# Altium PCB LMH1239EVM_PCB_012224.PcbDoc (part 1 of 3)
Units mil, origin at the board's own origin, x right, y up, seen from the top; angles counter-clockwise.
Board outline 4000 x 4500 mil, 4 copper layers (Top Layer, L02_GND, L03_PWR, Bottom Layer), stack 61.395 mil thick; 161 components, 103 nets, 483 pads, 593 vias.
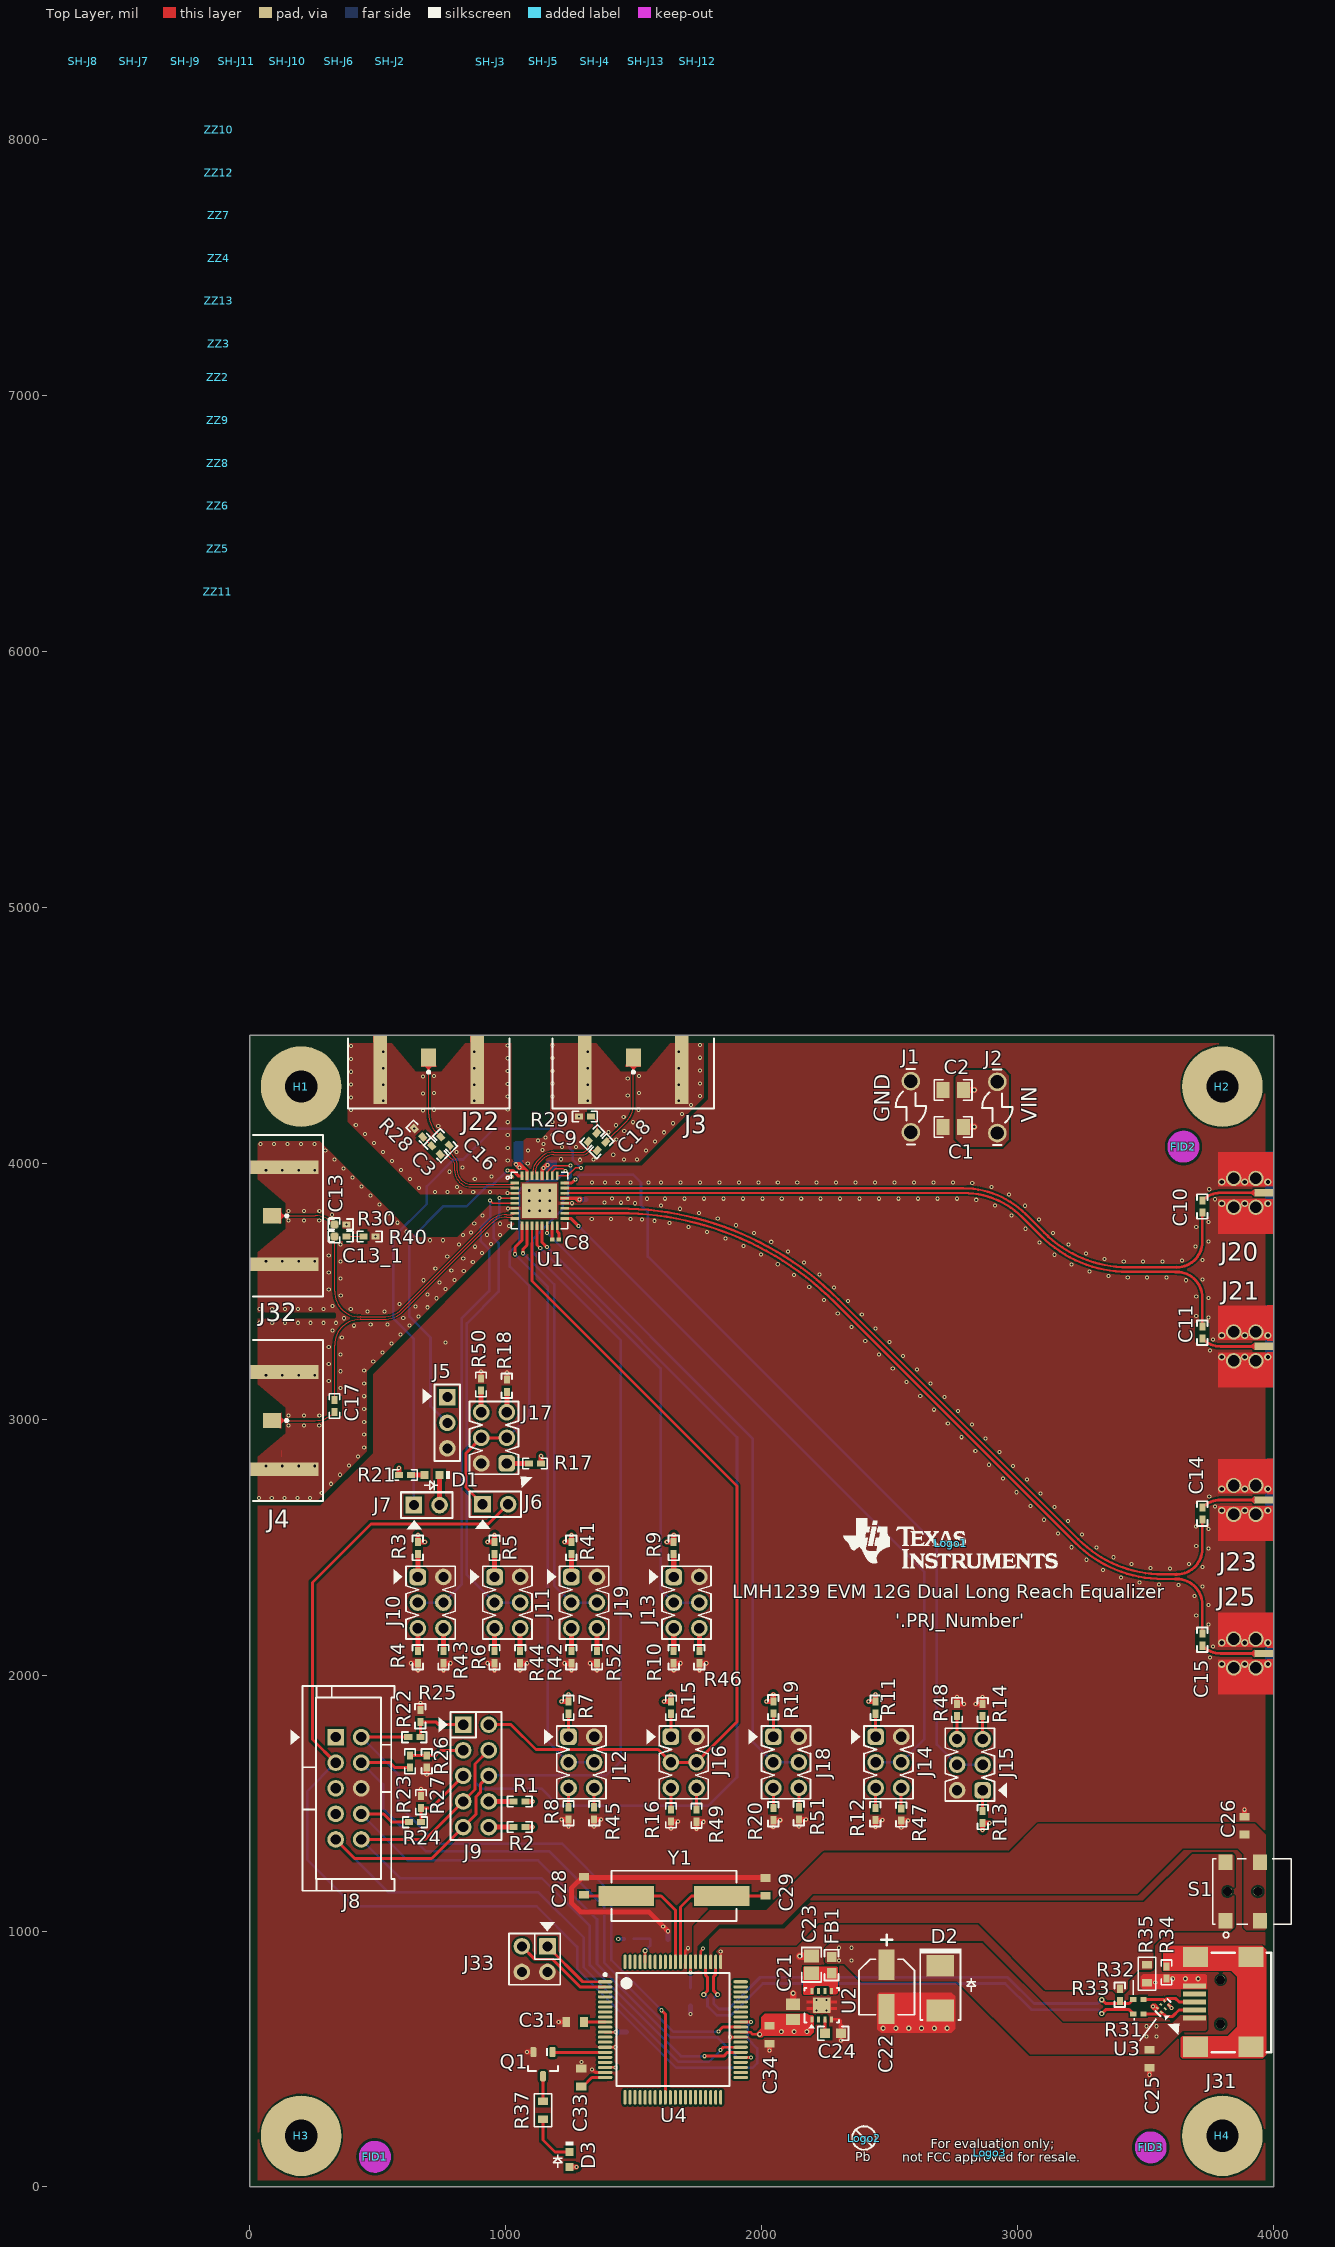
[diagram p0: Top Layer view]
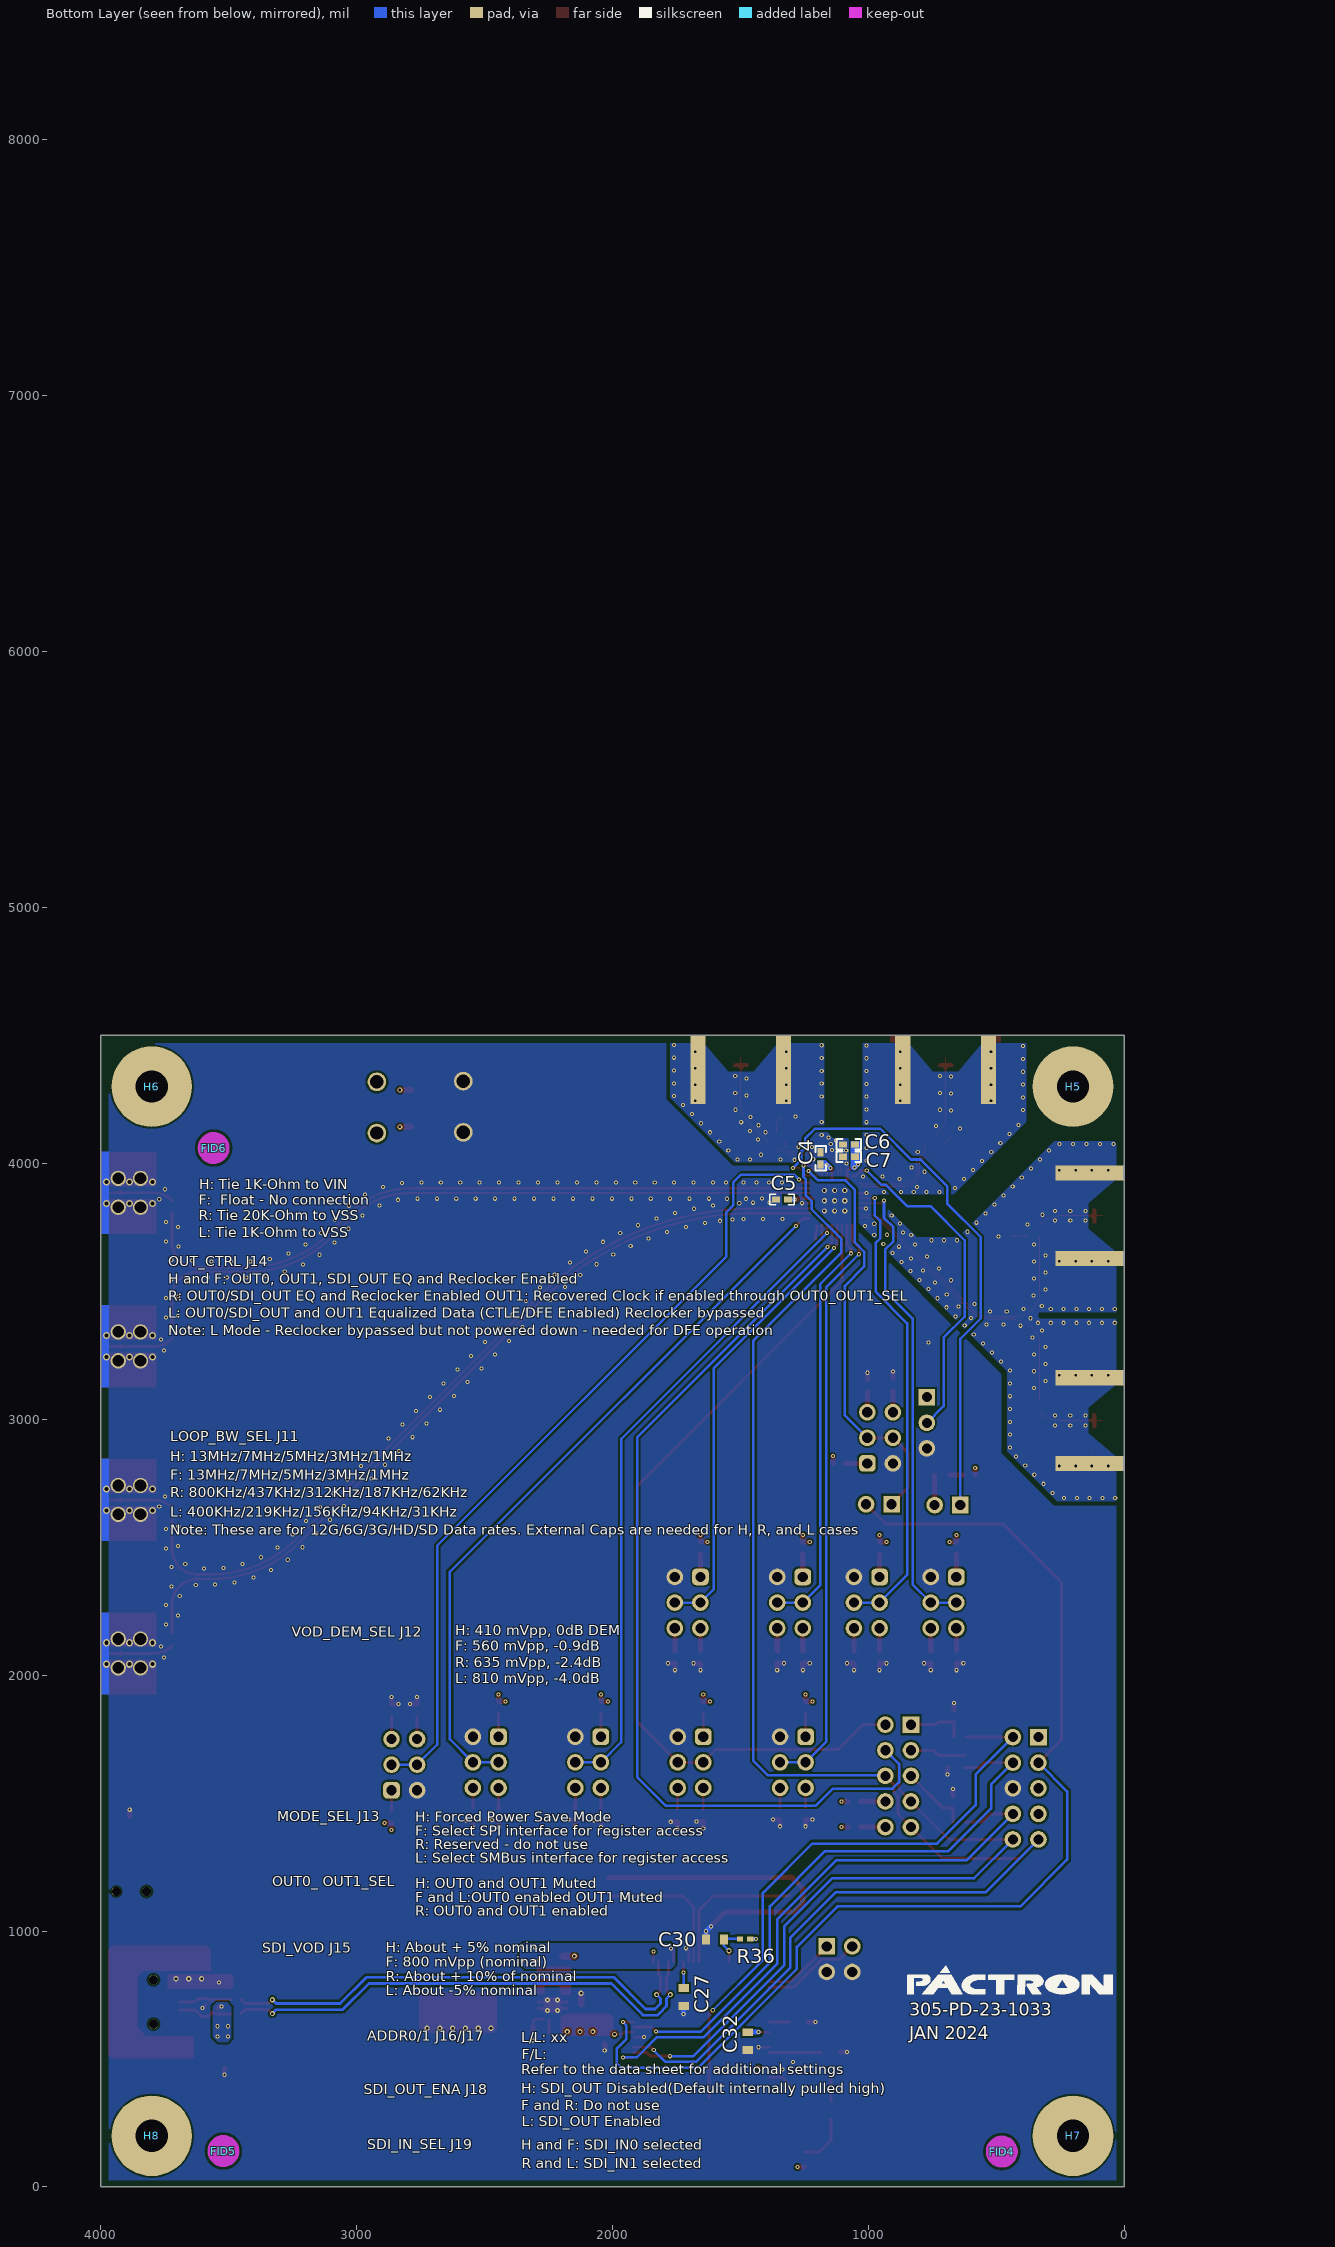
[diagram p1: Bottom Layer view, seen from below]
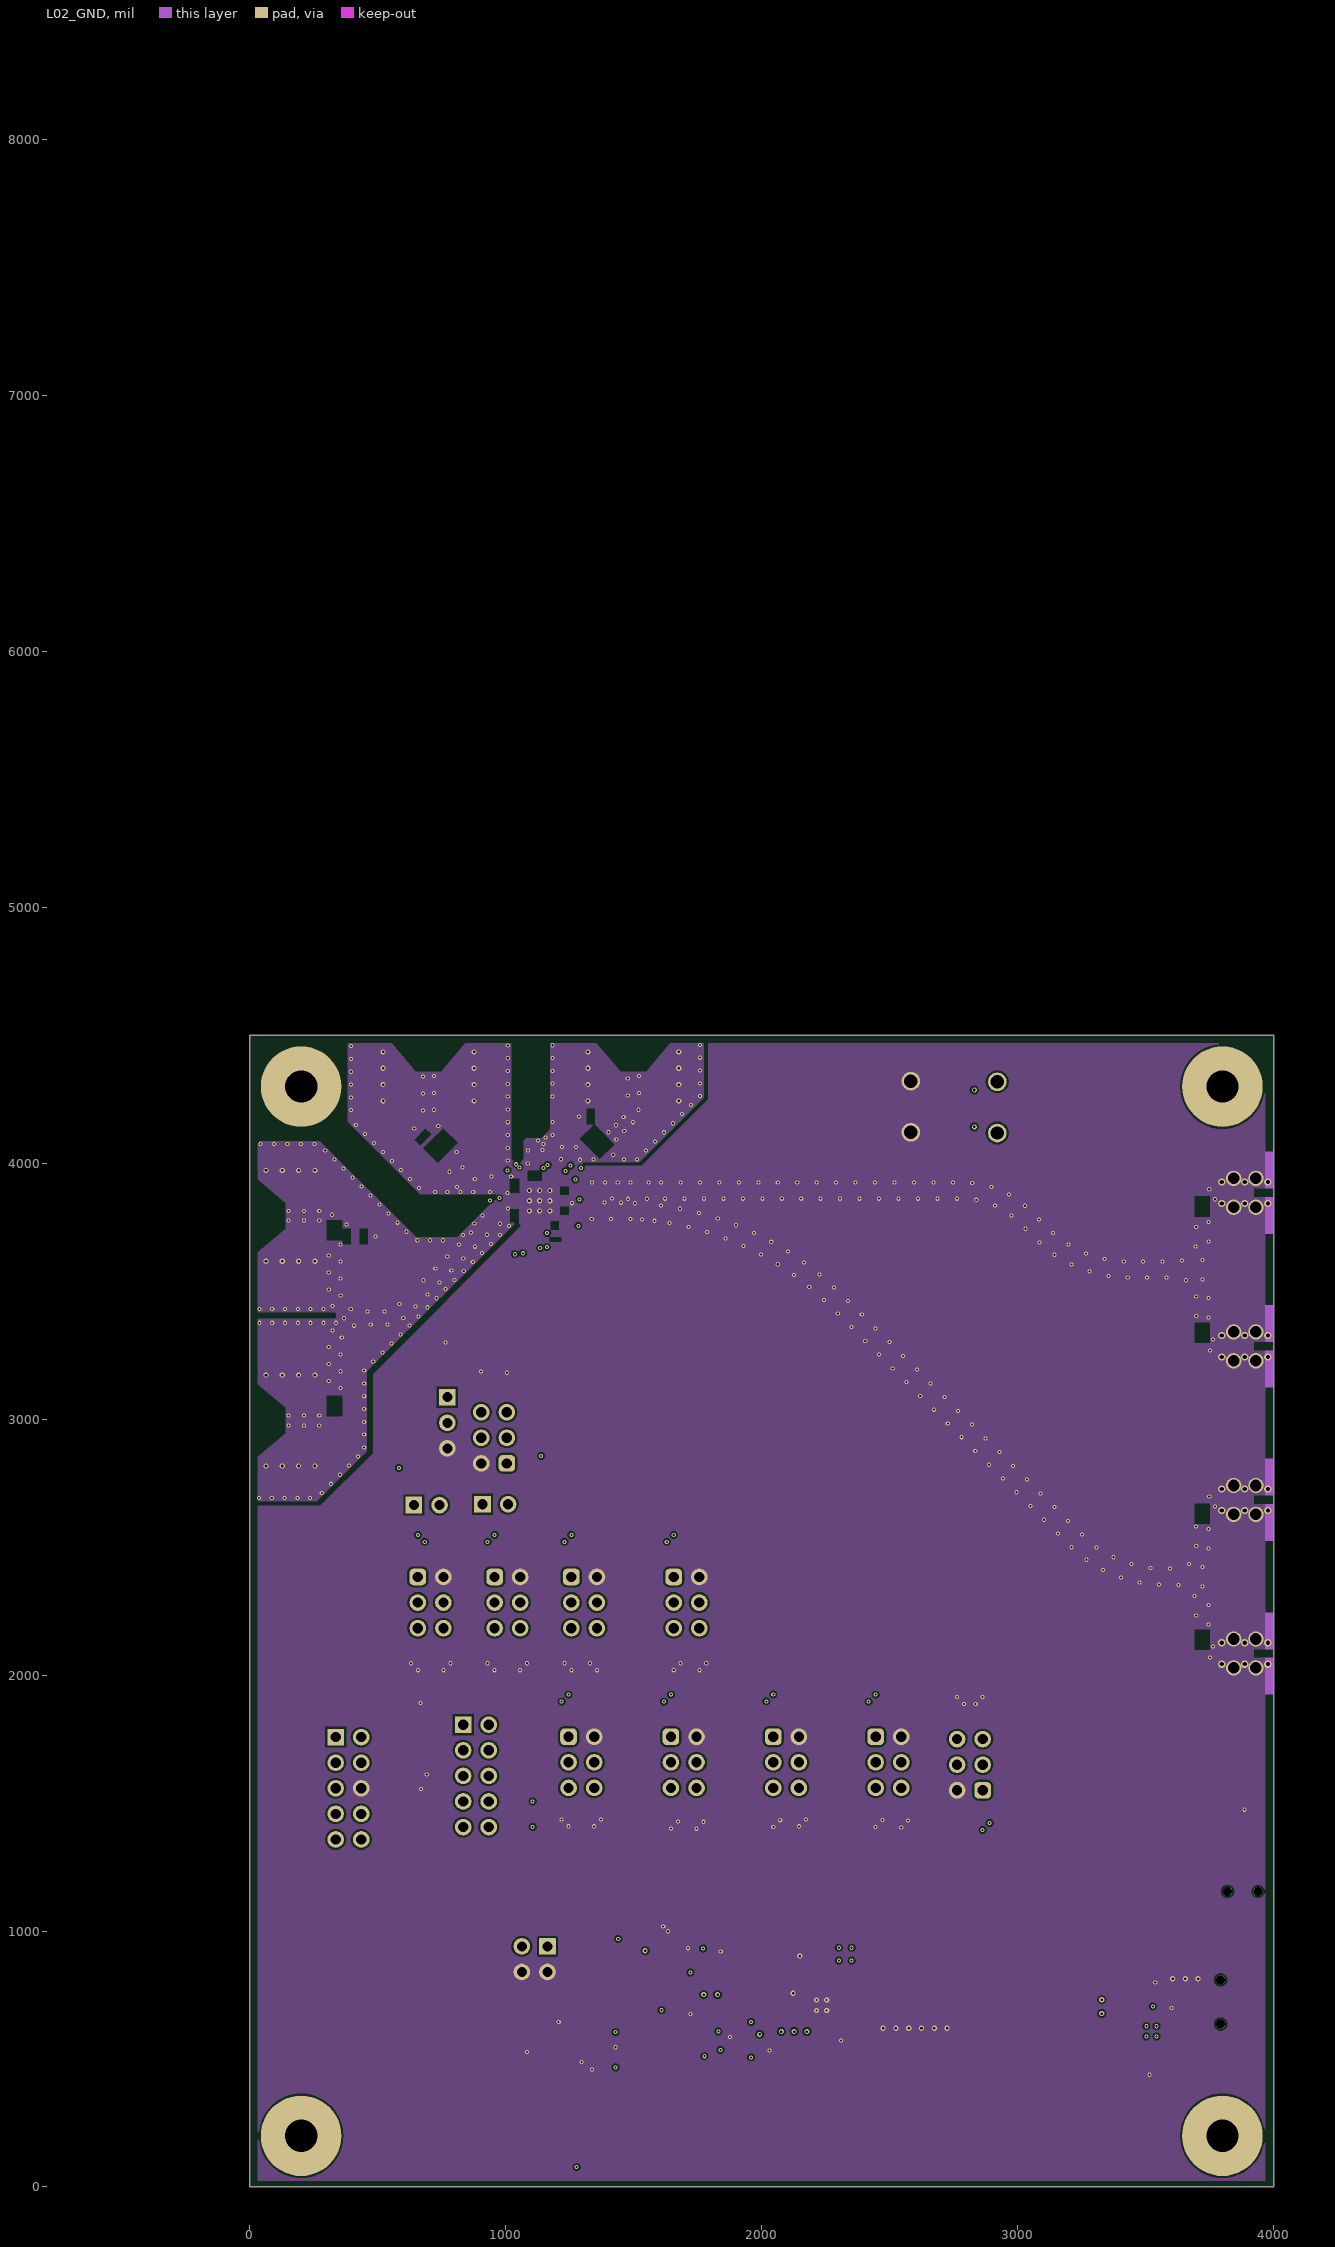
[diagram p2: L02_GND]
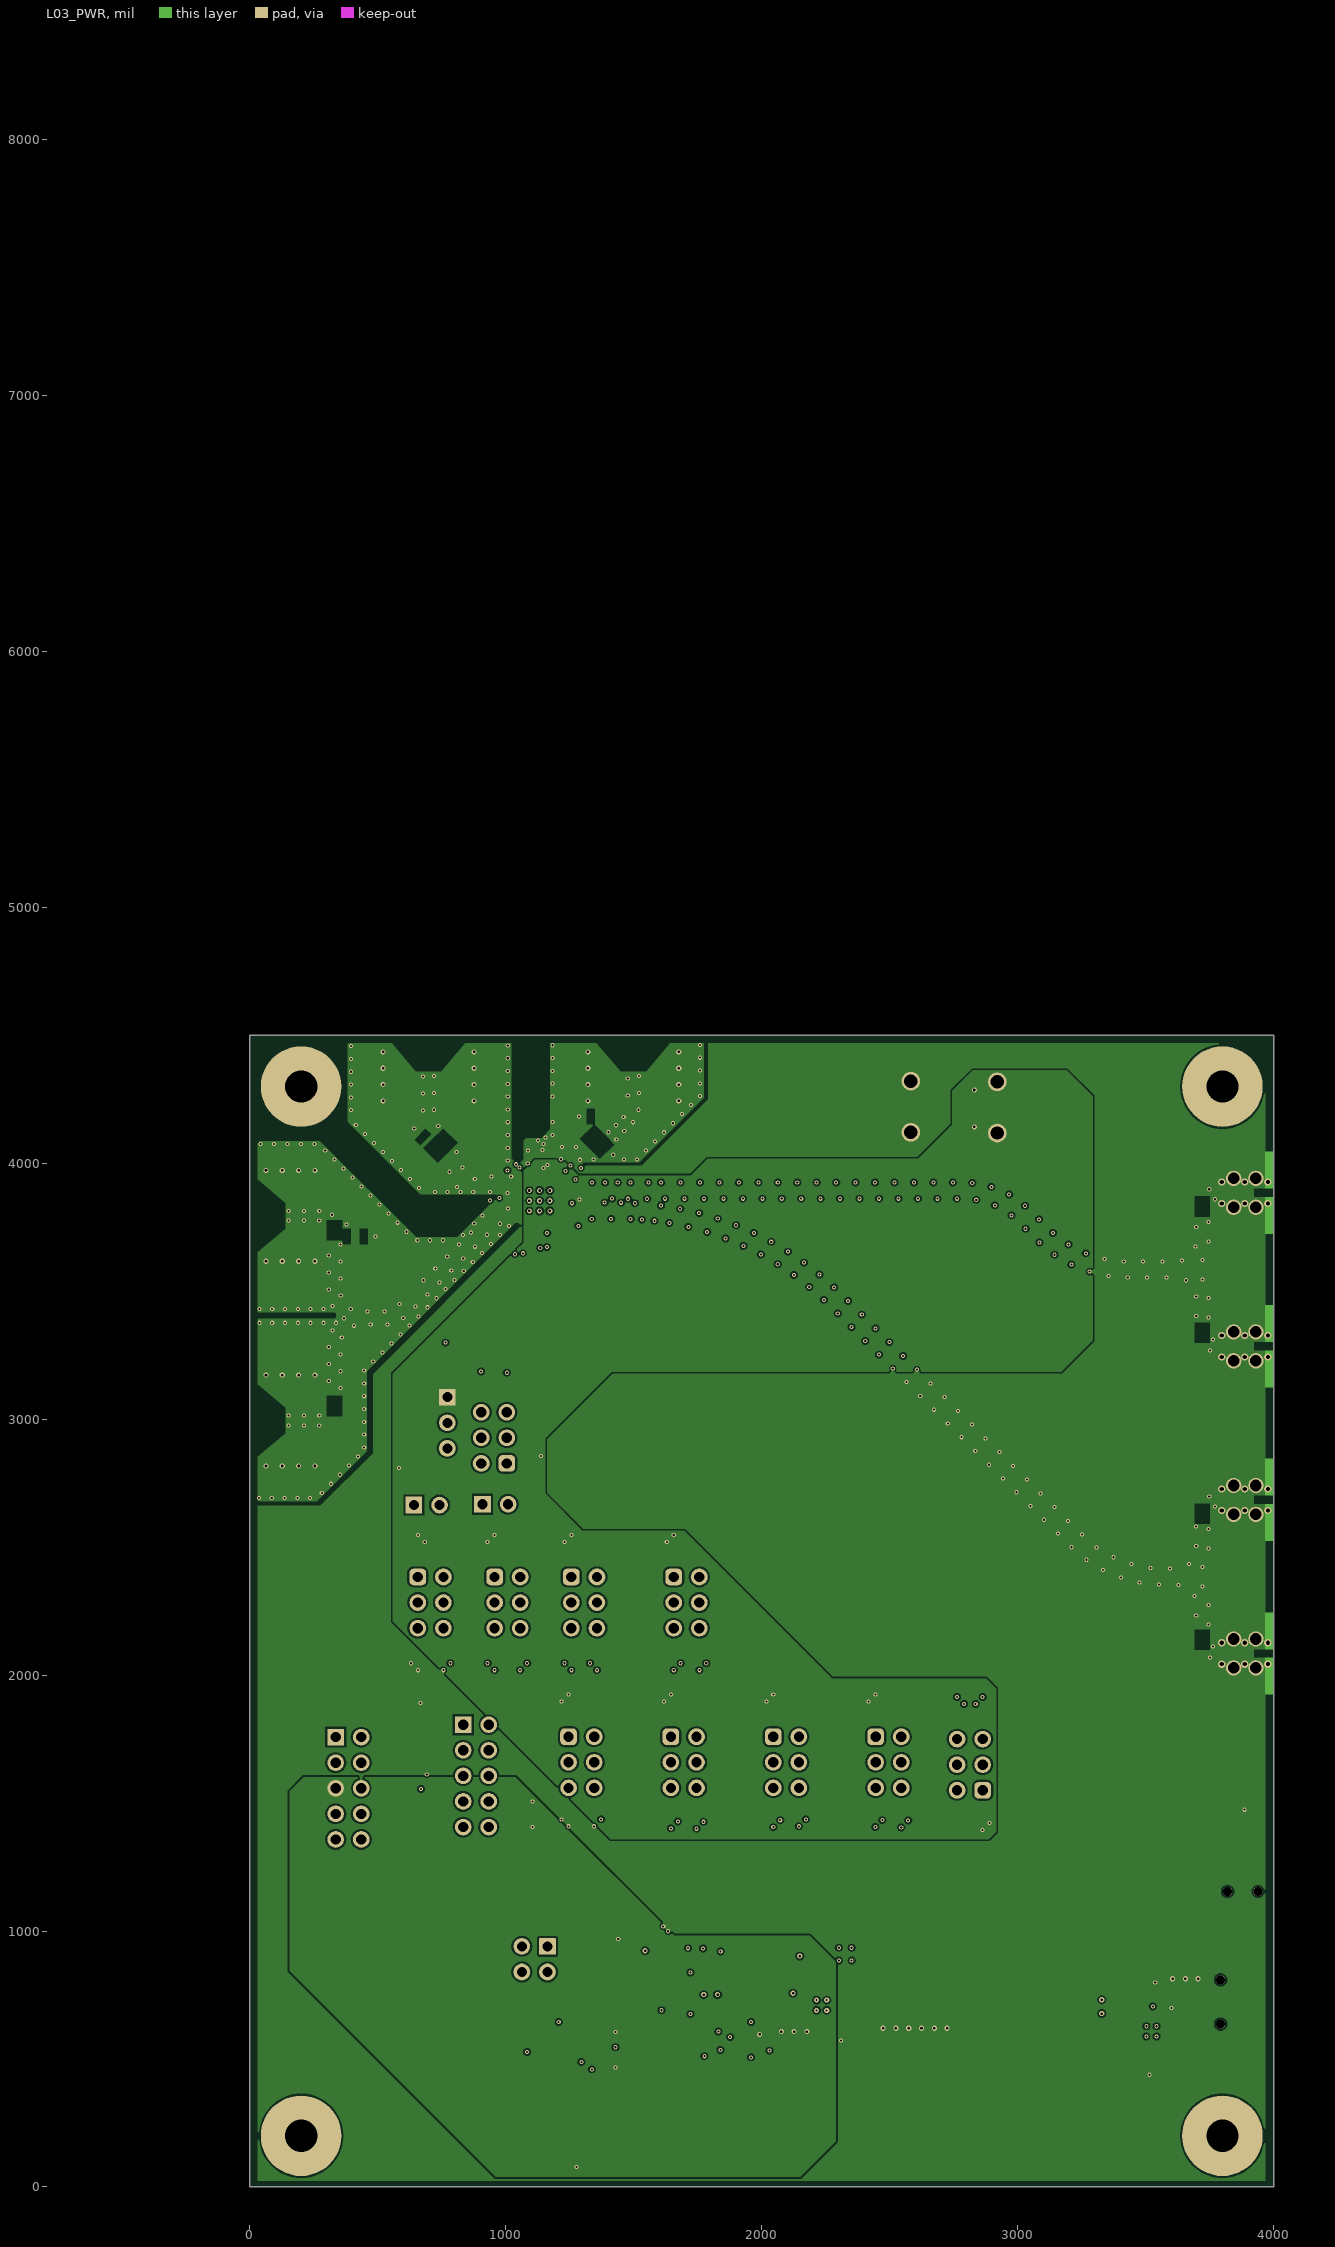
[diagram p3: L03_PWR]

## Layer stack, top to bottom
Top Solder: solder mask 0.4, Solder Resist, Dk 3.5
Top Layer: signal copper 1.4
Dielectric 1: prepreg 5.484, Megtron6, Dk 3.19
L02_GND: signal copper 1.4
Dielectric 2: core 44.813, FR-4 High Tg, Dk 3.89
L03_PWR: signal copper 1.4
Dielectric 3: prepreg 5.498, FR-4 High Tg, Dk 3.87
Bottom Layer: signal copper 1.4
Bottom Solder: solder mask 0.4, Solder Resist, Dk 3.5

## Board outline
0,0 0,4500 4000,4500 4000,0

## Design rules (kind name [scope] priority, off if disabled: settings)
AcuteAngle [All] p1: minimum=4.50000000000000E+0001 checktracksonly=FALSE
AssemblyTestPointUsage [All] p1: valid=2
BoardOutlineClearance BoardOutlineClearance_MountingHoles [OnCopper and InComponentClass('Mounting Holes')] p1: gap=39.37 ignorepadtopadclearanceinfootprint=FALSE
BoardOutlineClearance BoardOutlineClearance_Poly [OnCopper and IsPoly] p2: gap=25 ignorepadtopadclearanceinfootprint=FALSE except(30: Poly-OutlineEdge)
BoardOutlineClearance [OnCopper and Not InComponentClass('Logo') and not InComponentClass('FiducialMark') and not InRegion(1000,500,4000,800) and not InPoly] p3: gap=40 ignorepadtopadclearanceinfootprint=FALSE
Clearance Clearance_Keepouts [((IsTrack Or IsArc) And Not InPoly) And IsFree and IsKeepOut vs ((IsTrack Or IsArc) And Not InPoly) And IsFree and IsKeepOut] p1: gap=0 ignorepadtopadclearanceinfootprint=FALSE
Clearance Clearance_FiducialMark [IsKeepOut and InComponentClass('FiducialMark') vs IsPad and InComponentClass('FiducialMark')] p2: gap=0 ignorepadtopadclearanceinfootprint=FALSE
Clearance 100ohm_SE [(AsMils(Width) = 9.13)] p3: gap=7.87 ignorepadtopadclearanceinfootprint=TRUE except(8.44: Arc-Poly Track-Poly)
Clearance 100ohm_SE_1 [(AsMils(Width) = 8.85)] p4: gap=7.87 ignorepadtopadclearanceinfootprint=TRUE except(8.57: Arc-Poly Track-Poly)
Clearance 135ohm_DP [(AsMils(Width) = 3.5)] p5: gap=7.87 ignorepadtopadclearanceinfootprint=TRUE except(5.5: Track-Region; 6: Arc-Arc Arc-Track Arc-SMDPad Track-Track Track-SMDPad; 6.6: Arc-Poly Track-Poly; 6.8: Poly-Region; 7: Arc-Via Track-Via Poly-Poly)
Clearance 50ohm_SE [(AsMils(Width) = 8.74)] p6: gap=7.87 ignorepadtopadclearanceinfootprint=TRUE except(5.5: Track-Region; 6: Arc-Arc Arc-Track Track-Track; 6.43: Arc-Poly Track-Poly; 6.8: Poly-Region; 7: Poly-Poly)
Clearance 75ohm_SE_1 [(AsMils(Width) = 8.74)] p7: gap=7.87 ignorepadtopadclearanceinfootprint=TRUE except(6.43: Arc-Poly Track-Poly)
Clearance 150ohm_SE [(AsMils(Width) = 4.3) vs OnLayer('Top Layer')] p8: gap=7.87 ignorepadtopadclearanceinfootprint=TRUE except(5.5: Arc-Arc Arc-Track Arc-Region Track-Track Track-Region; 6.8: Region-Region; 8: Arc-Poly Track-Poly)
Clearance 50ohm_SE_1 [(AsMils(Width) = 10.96) vs OnLayer('Top Layer')] p9: gap=7.87 ignorepadtopadclearanceinfootprint=TRUE except(7: Arc-Arc Arc-Region; 8.51: Arc-Poly Track-Poly)
Clearance 90ohm_Diff_T [(AsMils(Width) = 11.98)] p10: gap=7.87 ignorepadtopadclearanceinfootprint=TRUE except(7.1: Track-SMDPad; 7.7: Track-Region; 8.01: Arc-Poly Track-Poly)
Clearance 90ohm_Diff_B [(AsMils(Width) = 10.57)] p11: gap=7.87 ignorepadtopadclearanceinfootprint=TRUE except(8.71: Arc-Poly Track-Poly)
Clearance SE_Coplaner [(AsMils(Width) = 10.784) vs OnLayer('Top Layer')] p12: gap=7.87 ignorepadtopadclearanceinfootprint=TRUE except(7.1: Arc-Region; 7.22: Arc-Arc; 8.61: Arc-Poly Track-Poly)
Clearance [All] p13: gap=7.87 ignorepadtopadclearanceinfootprint=TRUE except(4.96: Track-Via; 5.5: Region-Region; 6: Arc-Track Arc-SMDPad Track-Track Track-SMDPad Track-Region Via-Region; 6.8: Poly-Region; 7: Arc-Arc Arc-Via Arc-Region SMDPad-Region Via-Poly; 9.57: Arc-Poly Track-Poly)
ComponentClearance ComponentClearance_MountingHoles_FiducialMarks [InComponentClass('Mounting Holes') vs InComponentClass('FiducialMark')] p1: gap=50 collisioncheckmode=3 verticalgap=10 showdistances=FALSE
ComponentClearance ComponentClearance_Shunt [InComponentClass('Header') vs InComponentClass('Shunt')] p2: gap=0 collisioncheckmode=3 verticalgap=0 showdistances=FALSE
ComponentClearance ComponentClearance_Logo [InComponentClass('Logo')] p3: gap=30 collisioncheckmode=3 verticalgap=10 showdistances=FALSE
ComponentClearance ComponentClearance_ScrewToNut [(HasFootprint('NY PMS 440 0025 PH')) vs (HasFootprint('Keystone_1902C'))] p4: gap=5 collisioncheckmode=3 verticalgap=10 showdistances=FALSE
ComponentClearance ComponentClearance_MountingHoles [InComponentClass('Mounting Holes')] p5: gap=50 collisioncheckmode=3 verticalgap=100000 showdistances=FALSE
ComponentClearance ComponentClearance_SmallPassives [HasFootprint('0201*') or HasFootprint('0402*') or HasFootprint('0508') or HasFootprint('0603*') or HasFootprint('0612') or HasFootprint('0805*') or HasFootprint('0815*') or HasFootprint('0830*') or HasFootprint('1206*') or HasFootprint('1210*') or HasFootprint('1808*') or HasFootprint('1812*') or HasFootprint('1825*') or HasFootprint('2010*') or HasFootprint('2220*') or HasFootprint('2225*') or HasFootprint('2512*') or HasFootprint('2728*') or HasFootprint('3518*') vs HasFootprint('0201*') or HasFootprint('0402*') or HasFootprint('0508') or HasFootprint('0603*') or HasFootprint('0612') or HasFootprint('0805*') or HasFootprint('0815*') or HasFootprint('0830*') or HasFootprint('1206*') or HasFootprint('1210*') or HasFootprint('1808*') or HasFootprint('1812*') or HasFootprint('1825*') or HasFootprint('2010*') or HasFootprint('2220*') or HasFootprint('2225*') or HasFootprint('2512*') or HasFootprint('2728*') or HasFootprint('3518*')] p6: gap=14.96 collisioncheckmode=3 verticalgap=10 showdistances=FALSE
ComponentClearance ComponentClearance_THtoSMT [IsThruComponent vs IsSMTComponent] p7: gap=30 collisioncheckmode=3 verticalgap=30 showdistances=FALSE
ComponentClearance ComponentClearance_THtoTH [IsThruComponent vs IsThruComponent] p8: gap=20 collisioncheckmode=3 verticalgap=30 showdistances=FALSE
ComponentClearance [All] p9: gap=20 collisioncheckmode=3 verticalgap=10 showdistances=FALSE
DiffPairsRouting "135 Ohm" [InDifferentialPairClass('135 Ohm')] p1: maxlimit=13.45 minlimit=6.5 mostfreqgap=13.45 toplayer_maxgap=6.5 toplayer_prefgap=6.5 toplayer_minwidth=3.5 toplayer_maxwidth=3.5 toplayer_prefwidth=3.5 midlayer1_mingap=13.45 midlayer1_minwidth=10.55 midlayer1_maxwidth=10.55 midlayer1_prefwidth=10.55 midlayer2_mingap=13.45 midlayer2_minwidth=10.55 midlayer2_maxwidth=10.55 midlayer2_prefwidth=10.55 bottomlayer_mingap=13.43 bottomlayer_maxgap=13.43 bottomlayer_prefgap=13.43 bottomlayer_minwidth=10.57 bottomlayer_maxwidth=10.57 bottomlayer_prefwidth=10.57 maxuncoupledlength=1000
DiffPairsRouting "90 Ohm" [InDifferentialPairClass('90 Ohm')] p2: maxlimit=13.45 minlimit=10 mostfreqgap=13.45 toplayer_mingap=12.02 toplayer_maxgap=12.02 toplayer_prefgap=12.02 toplayer_minwidth=11.98 toplayer_maxwidth=11.98 toplayer_prefwidth=11.98 midlayer1_maxgap=10 midlayer1_prefgap=10 midlayer1_minwidth=15 midlayer1_maxwidth=15 midlayer1_prefwidth=15 midlayer2_maxgap=10 midlayer2_prefgap=10 midlayer2_minwidth=15 midlayer2_maxwidth=15 midlayer2_prefwidth=15 bottomlayer_mingap=13.45 bottomlayer_minwidth=10.55 bottomlayer_maxwidth=10.55 bottomlayer_prefwidth=10.55 maxuncoupledlength=500
DiffPairsRouting "100 Ohm" [InDifferentialPairClass('100 Ohm')] p3: maxlimit=12.47 minlimit=9.15 mostfreqgap=12.47 toplayer_maxgap=9.15 toplayer_prefgap=9.15 toplayer_minwidth=8.85 toplayer_maxwidth=8.85 toplayer_prefwidth=8.85 midlayer1_mingap=12.47 midlayer1_minwidth=3.53 midlayer1_maxwidth=3.53 midlayer1_prefwidth=3.53 midlayer2_mingap=12.47 midlayer2_minwidth=3.53 midlayer2_maxwidth=3.53 midlayer2_prefwidth=3.53 bottomlayer_mingap=12.47 bottomlayer_minwidth=3.53 bottomlayer_maxwidth=3.53 bottomlayer_prefwidth=3.53 maxuncoupledlength=1100
FabricationTestPointUsage TestPointUsage [All] p1: valid=2 allowmultiple=FALSE
FabricationTestpoint Testpoint [All] p1: side=3 testpointundercomponent=TRUE minsize=40 maxsize=100 preferedsize=60 minholesize=0 maxholesize=40 preferedholesize=32 testpointgrid=1 allowsidetop=TRUE allowsidebottom=TRUE usegrid=TRUE gridtolerance=0.01
FanoutControl Fanout_LCC [IsLCC] p1: bgadir=Out bgaviamode=Centered fanoutstyle=Auto fanoutdirection=Alternating viagrid=1 // Fanout_LCC (Default Rule)
FanoutControl Fanout_BGA [IsBGA] p2: bgadir=Out bgaviamode=Centered fanoutstyle=Auto fanoutdirection=Alternating viagrid=1 // Fanout_BGA (Default Rule)
FanoutControl Fanout_Default [All] p4: bgadir=Out bgaviamode=Centered fanoutstyle=Auto fanoutdirection=Alternating viagrid=1 // Fanout_Default (Default Rule)
FanoutControl Fanout_Small [(CompPinCount < 5)] p5: bgadir=Out bgaviamode=Centered fanoutstyle=Auto fanoutdirection=OutThenIn viagrid=1 // Fanout_Small (Default Rule)
HoleSize [All] p1: absolutevalues=TRUE maxlimit=251 minlimit=7.87 maxpercent=80.000 minpercent=20.000
MinimumAnnularRing MinimumAnnularRing_ThermalPadVias [IsVia and InAnyComponent] p1: minimumring=3
MinimumAnnularRing [All] p2: minimumring=3
MinimumSolderMaskSliver MinimumSolderMaskSliver_Logo [InComponentClass('Logo') vs InComponentClass('Logo')] p1: minsoldermaskwidth=0.7
MinimumSolderMaskSliver [All] p2: minsoldermaskwidth=3.94
PlaneConnect [All] p1: planeconnectstyle=Direct reliefexpansion=10 reliefentries=4 reliefconductorwidth=10 reliefairgap=10
PolygonConnect [All] p1: connectstyle=Direct reliefconductorwidth=10 reliefentries=4 polygonreliefangle="90 Angle" airgapwidth=10
RoutingVias ThermalPadVias [IsVia and InAnyComponent] p1: holewidth=7.87 width=19.68 viastyle="Through Hole" minholewidth=7.87 minwidth=19.68 maxholewidth=12.99 maxwidth=23.62
RoutingVias [All] p2: holewidth=16 width=34 viastyle="Through Hole" minholewidth=7.87 minwidth=24 maxholewidth=40 maxwidth=65
SilkToBoardRegionClearance [Not ((IsComment or IsDesignator) And (Hide <> 'False')) and not InRegion(1000,500,4000,800)] p1:
SilkToSilkClearance SilkToSilkClearance_Pb-FreeLogo [(HasFootprint('Pb-Free_Overlay_Medium') OR HasFootprint('Pb-Free_Overlay_Small')) vs (HasFootprint('Pb-Free_Overlay_Medium') OR HasFootprint('Pb-Free_Overlay_Small'))] p1: silktosilkclearance=0
SilkToSilkClearance [All] p2: silktosilkclearance=3.94
SilkToSolderMaskClearance SilkToComponentPadClearance [(IsPad or IsFill or IsRegion) and InAnycomponent] p1: minsilkscreentomaskgap=5 clearancetoexposedcopper=TRUE
SilkToSolderMaskClearance "Silk to Solder Mask Opening" [All] p2: minsilkscreentomaskgap=3.94 clearancetoexposedcopper=FALSE
SolderMaskExpansion [All] p1: expansion=1.97 istentingtop=FALSE
UnRoutedNet [All] p1: checkbadconnections=TRUE
Width [All] p1: maxlimit=100 minlimit=3.53 preferedwidth=10 checkconnectedcopper=TRUE
14 further rules are at their usual default settings.

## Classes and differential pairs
net class SDI_OUT: NetC13_2 NetC17_2 SDI_OUT+ SDI_OUT-
net class SDI_IN: NetC16_2 NetC18_2 SDI_IN0+ SDI_IN0- SDI_IN1+ SDI_IN1-
differential pair class "100 Ohm": NetC10-11_1 NetC14-15_1 NewDifferentialPair1 NewDifferentialPair2 OUT0_PN OUT1_PN
net class NewClass: NetC10_1 NetC11_1 NetC14_1 NetC15_1 OUT0_N OUT0_P OUT1_N OUT1_P
differential pair class "90 Ohm": NewDifferentialPair8
differential pair class "135 Ohm": NetC3-9_2 NetC16-18_2 SDI_IN0+- SDI_IN1+- SDI_OUT+-
component class Shunt: SH-J2 SH-J3 SH-J4 SH-J5 SH-J6 SH-J7 SH-J8 SH-J9 SH-J10 SH-J11 SH-J12 SH-J13
component class LMH1239EVM_Page1_DUT: C1 C2 C3 C4 C5 C6 C7 C8 C9 C10 C11 C13 C13_1 C14 C15 C16 C17 C18 D1 J1 J2 J3 J4 J5 J6 J7 J8 J9 J10 J11 J12 J13 J14 J15 J16 J17 J18 J19 J20 J21 J22 J23 J25 J32 R1 R2 R3 R4 R5 R6 R7 R8 R9 R10 R11 R12 R13 R14 R15 R16 R17 R18 R19 R20 R21 R22 R23 R24 R25 R26 R27 R28 R29 R30 R40 R41 R42 R43 R44 R45 R46 R47 R48 R49 R50 R51 R52 U1
component class LMH1239EVM_Page2_MCU: C21 C22 C23 C24 C25 C26 C27 C28 C29 C30 C31 C32 C33 C34 D2 D3 FB1 J31 J33 Q1 R31 R32 R33 R34 R35 R36 R37 S1 U2 U3 U4 Y1
component class Header: J5 J6 J7 J9 J10 J11 J12 J13 J14 J15 J16 J17 J18 J19 J33
component class "Mounting Holes": H1 H2 H3 H4
component class Logo: Logo1
component class LMH1239EVM_Page3_SILKSCREEN: FID1 FID2 FID3 FID4 FID5 FID6 H1 H2 H3 H4 H5 H6 H7 H8 Logo1 Logo2 Logo3 SH-J2 SH-J3 SH-J4 SH-J5 SH-J6 SH-J7 SH-J8 SH-J9 SH-J10 SH-J11 SH-J12 SH-J13 ZZ2 ZZ3 ZZ4 ZZ5 ZZ6 ZZ7 ZZ8 ZZ9 ZZ10 ZZ11 ZZ12 ZZ13
component class FiducialMark: FID1 FID2 FID3 FID4 FID5 FID6
component class AssemblyNote: ZZ2 ZZ3 ZZ4 ZZ5 ZZ6 ZZ7 ZZ8 ZZ9 ZZ10 ZZ11 ZZ12 ZZ13
differential pair NewDifferentialPair2: +"" -""
differential pair NewDifferentialPair1: +"" -""
differential pair 2xCal: +"" -""
differential pair 2xCal2: +"" -""
differential pair NetC36-37: +"" -""
differential pair Cal2_PN: +"" -""
differential pair NetC14-15_1: +NetC14_1 -NetC15_1
differential pair NetC10-11_1: +NetC10_1 -NetC11_1
differential pair OUT1_PN: +OUT1_P -OUT1_N
differential pair OUT0_PN: +OUT0_P -OUT0_N
differential pair NetC3-9_2: +NetC3_2 -NetC9_2
differential pair NetC16-18_2: +NetC16_2 -NetC18_2
differential pair SDI_IN1+-: +SDI_IN1+ -SDI_IN1-
differential pair SDI_IN0+-: +SDI_IN0+ -SDI_IN0-
differential pair SDI_OUT+-: +SDI_OUT+ -SDI_OUT-
differential pair Cal: +"" -""
differential pair DPDM: +DP -DM
differential pair NetJ31: +NetJ31_3 -NetJ31_2

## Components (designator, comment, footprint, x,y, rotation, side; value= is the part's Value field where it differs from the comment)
C1 "0805YD106MAT2A" 0805_HV 2747.98,4142.46 r0 top value=10uF
C2 "0805YD105KAT2A" 0805_HV 2747.98,4286.67 r0 top value=1uF
C3 "C1005X5R1A475K050BC" 0402#1 726.96,4051.79 r135 top value=4.7uF
C4 "C1005X5R0J104K050BA" 0402#1 1185.95,4019.9 r90 bottom value=0.1uF
C5 "C1005X5R0J104K050BA" 0402#1 1337,3858.88 r0 bottom value=0.1uF
C6 "C1005X5R0J105M" 0402#1 1076.04,4074.45 r0 bottom value=1uF
C7 "C1005X5R0J104K050BA" 0402#1 1076.04,4025.94 r0 bottom value=0.1uF
C8 "EMK063BBJ474KPLF" 0201 1194.07,3702.83 r0 top value=0.47uF
C9 "C1005X5R1A475K050BC" 0402#1 1338.56,4102.5 r45 top value=4.7uF
C10 "C1005X5R1A475K050BC" 0402#1 3721.5,3831.31 r270 top value=4.7uF
C11 "C1005X5R1A475K050BC" 0402#1 3721.5,3338.56 r90 top value=4.7uF
C13 "C1005X5R1A475K050BC" 0402#1 330.56,3738.26 r90 top value=4.7uF
C13_1 "C1005X5R1A475K050BC" 0402#1 354.18,3714.64 r0 top value=4.7uF
C14 "C1005X5R1A475K050BC" 0402#1 3721.5,2631.31 r270 top value=4.7uF
C15 "C1005X5R1A475K050BC" 0402#1 3721.5,2138.56 r90 top value=4.7uF
C16 "C1005X5R1A475K050BC" 0402#1 762.32,4087.14 r135 top value=4.7uF
C17 "C1005X5R1A475K050BC" 0402#1 330.56,3052.1 r270 top value=4.7uF
C18 "C1005X5R1A475K050BC" 0402#1 1373.91,4067.15 r45 top value=4.7uF
C21 "0805YD225KAT2A" C0805 2122.28,684.68 r270 top value=2.2uF
C22 "EMVE100ADA220ME55G" CAPSMT_62_E55 2488.12,781.73 r270 top value=22uF
C23 "0805YD105KAT2A" 0805 2194.21,868.74 r90 top value=1uF
C24 "C1608X7R1H103K" 0603 2278.5,600.27 r0 top value=0.01uF
C25 "0603YC104JAT2A" C603 3515.24,500.7 r90 top value=0.1uF
C26 "06035A221FAT2A" C603 3886.18,1412.18 r270 top value=220pF
C27 "06035A221FAT2A" C603 1721.5,742.6 r90 bottom value=220pF
C28 "GRM1885C2A300JA01D" C603 1305.35,1176.88 r90 top value=30pF
C29 "GRM1885C2A300JA01D" C603 2014.14,1172.51 r90 top value=30pF
C30 "C0603X222K5RACTU" C603 1599.06,967.19 r180 bottom value=2200pF
C31 "0603YC104JAT2A" C603 1270.35,644.53 r0 top value=0.1uF
C32 "0603YC104JAT2A" C603 1471.5,570.16 r90 bottom value=0.1uF
C33 "GRM188R71A474KA61D" C603 1295,427.99 r270 top value=0.47uF
C34 "0603YC104JAT2A" C603 2030,595 r90 top value=0.1uF
D1 "SML-LX0603GW-TR" LED_SML-LX0603GW 711.21,2782.36 r0 top value=Green
D2 "1SMB5922BT3G" SMB 2698.12,777.12 r270 top value=7.5V
D3 "SML-LX0603GW-TR" LED_SML-LX0603GW 1249.46,107.06 r90 top value=Green
FB1 "MI0603J600R-10" 0603 2272.71,866.77 r270 top value="60 ohm"
FID1 "Fiducial" Fiducial10-30 488.22,118.12 r0 top
FID2 "Fiducial" Fiducial10-30 3647.89,4065.21 r0 top
FID3 "Fiducial" Fiducial10-30 3520,155 r0 top
FID4 "Fiducial" Fiducial10-30 478.22,138.12 r90 bottom
FID5 "Fiducial" Fiducial10-30 3520,140.51 r90 bottom
FID6 "Fiducial" Fiducial10-30 3558,4060 r90 bottom
H1 "NY PMS 440 0025 PH" "NY PMS 440 0025 PH" 200,4300 r0 top locked
H2 "NY PMS 440 0025 PH" "NY PMS 440 0025 PH" 3800,4300 r0 top locked
H3 "NY PMS 440 0025 PH" "NY PMS 440 0025 PH" 200,200 r0 top locked
H4 "NY PMS 440 0025 PH" "NY PMS 440 0025 PH" 3800,200 r0 top locked
H5 "1902C" Keystone_1902C 200,4300 r180 bottom
H6 "1902C" Keystone_1902C 3800,4300 r180 bottom locked
H7 "1902C" Keystone_1902C 200,200 r180 bottom
H8 "1902C" Keystone_1902C 3800,200 r180 bottom
J1 "1212-ST" Keystone_1212-ST 2582.66,4221.43 r90 top
J2 "1212-ST" Keystone_1212-ST 2920.29,4218.64 r270 top
J3 "BNC7T-J-P-GN-ST-EM1D" SAMTEC_BNC7T-J-P-GN-ST-EM1D 1498.12,4500 r0 top locked
J4 "BNC7T-J-P-GN-ST-EM1D" SAMTEC_BNC7T-J-P-GN-ST-EM1D 0,2995.18 r90 top locked
J5 "5-146278-3" TE_5-146278-3 771.1,2986.27 r270 top
J6 "5-146278-2" TE_5-146278-2 958.78,2668.11 r0 top
J7 "5-146278-2" TE_5-146278-2 690.74,2664.85 r0 top
J8 "5103308-1" CONN_5103308-1 384.99,1558.01 r270 top
J9 "PEC05DAAN" CONN_PEC05DAAN 883.21,1606.52 r270 top
J10 "5-146254-3" TE_5-146254-3 705.97,2283.85 r270 top
J11 "5-146254-3" TE_5-146254-3 1005.97,2283.85 r270 top
J12 "5-146254-3" TE_5-146254-3 1295,1659.42 r270 top
J13 "5-146254-3" TE_5-146254-3 1705.97,2283.85 r270 top
J14 "5-146254-3" TE_5-146254-3 2495,1659.42 r270 top
J15 "5-146254-3" TE_5-146254-3 2813.21,1650.33 r90 top
J16 "5-146254-3" TE_5-146254-3 1695,1659.42 r270 top
J17 "5-146254-3" TE_5-146254-3 953.78,2927.55 r90 top
J18 "5-146254-3" TE_5-146254-3 2095,1659.42 r270 top
J19 "5-146254-3" TE_5-146254-3 1305.97,2283.85 r270 top
J20 "142-0771-821" EMERSON_142-0771-821 3887.5,3884.93 r270 top locked
J21 "142-0771-821" EMERSON_142-0771-821 3887.5,3284.93 r270 top locked
J22 "" SAMTEC_BNC7T-J-P-GN-ST-EM1D 698.12,4499.99 r0 top locked
J23 "142-0771-821" EMERSON_142-0771-821 3887.5,2684.94 r270 top locked
J25 "142-0771-821" EMERSON_142-0771-821 3887.5,2084.94 r270 top locked
J31 "USB Mini Type B" CONN_USB-MINI-B-1734035-2 3793.27,722.95 r90 top
J32 "" SAMTEC_BNC7T-J-P-GN-ST-EM1D 0,3795.18 r90 top locked
J33 "TSW-102-07-G-D" TSW-102-07-G-D 1112.6,890.2 r180 top
Logo1 "Texas Instruments" TI_Stacked_Overlay_Small 2737.58,2515.2 r0 top
Logo2 "Pb-Free Symbol" Pb-Free_Overlay_Small 2399.6,191.38 r0 top
Logo3 "FCC disclaimer" FCC_disclaimer_stacked 2890.15,133.4 r0 top
Q1 "BSS138" SOT-23 1145,480 r270 top value=50V
R1 "CRCW04022K00FKED" 0402#1 1053.84,1506.52 r0 top value=2.00k
R2 "CRCW04022K00FKED" 0402#1 1053.84,1406.52 r0 top value=2.00k
R3 "CRCW04021K00FKED" 0402#1 655.97,2497.47 r270 top value=1.00k
R4 "CRCW04021K00FKED" 0402#1 655.97,2070.23 r90 top value=1.00k
R5 "CRCW04021K00FKED" 0402#1 955.97,2497.47 r270 top value=1.00k
R6 "CRCW04021K00FKED" 0402#1 955.97,2070.23 r90 top value=1.00k
R7 "CRCW04021K00FKED" 0402#1 1245,1873.04 r270 top value=1.00k
R8 "CRCW04021K00FKED" 0402#1 1245,1460.3 r90 top value=1.00k
R9 "CRCW04021K00FKED" 0402#1 1655.97,2497.47 r270 top value=1.00k
R10 "CRCW04021K00FKED" 0402#1 1655.97,2070.22 r90 top value=1.00k
R11 "CRCW04021K00FKED" 0402#1 2445,1873.04 r270 top value=1.00k
R12 "CRCW04021K00FKED" 0402#1 2443.98,1457.18 r90 top value=1.00k
R13 "CRCW04021K00FKED" 0402#1 2863.21,1445.8 r90 top value=1.00k
R14 "CRCW04021K00FKED" 0402#1 2863.21,1863.95 r270 top value=1.00k
R15 "CRCW04021K00FKED" 0402#1 1645,1873.04 r270 top value=1.00k
R16 "CRCW04021K00FKED" 0402#1 1645,1452.18 r90 top value=1.00k
R17 "CRCW04021K00FKED" 0402#1 1113.79,2827.29 r180 top value=1.00k
R18 "CRCW04021K00FKED" 0402#1 1003.78,3131.05 r270 top value=1.00k
R19 "CRCW04021K00FKED" 0402#1 2045,1874.22 r270 top value=1.00k
R20 "CRCW04021K00FKED" 0402#1 2045,1456.87 r90 top value=1.00k
R21 "CRCW0402220RJNED" 0402#1 605.84,2782.36 r0 top value=220
R22 "CRCW04023K16FKED" 0402#1 642.23,1758.01 r0 top value=3.16k
R23 "CRCW04023K16FKED" 0402#1 625.1,1663.13 r90 top value=3.16k
R24 "CRCW04023K16FKED" 0402#1 644.99,1425.5 r0 top value=3.16k
R25 "CRCW04029K76FKED" 0402#1 665.85,1840.1 r90 top value=9.76k
R26 "CRCW04029K76FKED" 0402#1 690.85,1663.13 r270 top value=9.76k
R27 "CRCW04029K76FKED" 0402#1 668.61,1504.12 r90 top value=9.76k
R28 "ERJ-PA2F75R0X" 0402#1 658.62,4120.13 r315 top value=75.0
R29 "ERJ-PA2F75R0X" 0402#1 1308.76,4183 r0 top value=75.0
R30 "ERJ-PA2F75R0X" 0402#1 354.18,3761.88 r180 top value=75.0
R31 "CRCW040233R0JNED" 0402#2 3471.41,676.46 r0 top value=33
R32 "CRCW040233R0JNED" 0402#2 3471.41,733.05 r0 top value=33
R33 "CRCW04021K50JNED" 0402#1 3399.3,751.12 r90 top value=1.5k
R34 "CRCW040233K0JNED" 0402#1 3581.85,838.63 r90 top value=33k
R35 "CRCW06031M20JNEA" R603 3505.49,833.69 r90 top value=1.2Meg
R36 "CRCW040233K0JNED" 0402#2 1480.95,969.31 r0 bottom value=33k
R37 "CRCW0603200RFKEA" R603 1145,300 r270 top value=200
R40 "ERJ-PA2F75R0X" 0402#1 467.63,3714.64 r180 top value=75.0
R41 "CRCW04021K00FKED" 0402#1 1255.97,2497.47 r270 top value=1.00k
R42 "CRCW04021K00FKED" 0402#1 1255.97,2070.22 r90 top value=1.00k
R43 "CRCW040220K0FKED" 0402#1 755.97,2070.23 r270 top value=20.0k
R44 "CRCW040220K0FKED" 0402#1 1055.97,2070.23 r270 top value=20.0k
R45 "CRCW040220K0FKED" 0402#1 1345,1460.3 r270 top value=20.0k
R46 "CRCW040220K0FKED" 0402#1 1755.97,2070.22 r270 top value=20.0k
R47 "CRCW040220K0FKED" 0402#1 2545,1455.8 r270 top value=20.0k
R48 "CRCW040220K0FKED" 0402#1 2763.21,1863.95 r90 top value=20.0k
R49 "CRCW040220K0FKED" 0402#1 1745,1450.8 r270 top value=20.0k
R50 "CRCW040220K0FKED" 0402#1 902.95,3136.05 r90 top value=20.0k
R51 "CRCW040220K0FKED" 0402#1 2145.03,1460.3 r270 top value=20.0k
R52 "CRCW040220K0FKED" 0402#1 1355.97,2070.23 r270 top value=20.0k
S1 "TL3901AGQF180" TL3901AGQF180 3879.6,1154.74 r0 top
SH-J2 "969102-0000-DA" SNT-100-BK-G 548.69,8307.33 r90 top value=1x2
SH-J3 "969102-0000-DA" SNT-100-BK-G 940.92,8305.54 r90 top value=1x2
SH-J4 "969102-0000-DA" SNT-100-BK-G 1349.1,8307.33 r90 top value=1x2
SH-J5 "969102-0000-DA" SNT-100-BK-G 1149,8307.33 r90 top value=1x2
SH-J6 "969102-0000-DA" SNT-100-BK-G 348.59,8307.33 r90 top value=1x2
SH-J7 "969102-0000-DA" SNT-100-BK-G -451.82,8307.33 r90 top value=1x2
SH-J8 "969102-0000-DA" SNT-100-BK-G -651.92,8307.33 r90 top value=1x2
SH-J9 "969102-0000-DA" SNT-100-BK-G -251.72,8307.33 r90 top value=1x2
SH-J10 "969102-0000-DA" SNT-100-BK-G 148.49,8307.33 r90 top value=1x2
SH-J11 "969102-0000-DA" SNT-100-BK-G -51.62,8307.33 r90 top value=1x2
SH-J12 "969102-0000-DA" SNT-100-BK-G 1749.31,8307.33 r90 top value=1x2
SH-J13 "969102-0000-DA" SNT-100-BK-G 1549.2,8307.33 r90 top value=1x2
U1 "LMH1239RTVR" RTV0032E-MFG 1131.87,3854.12 r0 top locked
U2 "TPS73533DRBR" DRB0008A 2234.21,710.27 r90 top
U3 "TPD4E004DRYR" DRY0006A 3567.98,704.96 r135 top
U4 "MSP430F5529IPN" PN0080A_N 1652.6,615 r0 top
Y1 "ECS-240-20-5PX-TR" XTAL_CSM-7X 1657.13,1137.51 r180 top
ZZ2 "Place Shunt Jumper: SH-J2 on J10 (pin3-5)" AssemblyNote -125,7071.13 r0 top
ZZ3 "Place Shunt Jumper: SH-J3 on J11 (pin1-2)" AssemblyNote -122,7202.76 r0 top
ZZ4 "Place Shunt Jumper: SH-J4 on J12 (pin1-3)" AssemblyNote -122,7537.39 r0 top
ZZ5 "Place Shunt Jumper: SH-J5 on J13 (pin3-5)" AssemblyNote -125,6401.86 r0 top
ZZ6 "Place Shunt Jumper: SH-J6 on J14 (pin3-4)" AssemblyNote -125,6569.18 r0 top
ZZ7 "Place Shunt Jumper: SH-J7 on J15 (pin3-4)" AssemblyNote -122,7704.71 r0 top
ZZ8 "Place Shunt Jumper: SH-J8 on J16 (pin3-5)" AssemblyNote -125,6736.5 r0 top
ZZ9 "Place Shunt Jumper: SH-J9 on J17 (pin3-5)" AssemblyNote -125,6903.81 r0 top
ZZ10 "Place Shunt Jumper: SH-J10 on J18 (pin3-5)" AssemblyNote -122,8039.34 r0 top
ZZ11 "Place Shunt Jumper: SH-J11 on J19 (pin3-4)" AssemblyNote -125,6234.55 r0 top
ZZ12 "Place Shunt Jumper: SH-J12 on J9 (pin7-8)" AssemblyNote -122,7872.03 r0 top
ZZ13 "Place Shunt Jumper: SH-J13 on J9 (pin9-10)" AssemblyNote -122,7370.08 r0 top

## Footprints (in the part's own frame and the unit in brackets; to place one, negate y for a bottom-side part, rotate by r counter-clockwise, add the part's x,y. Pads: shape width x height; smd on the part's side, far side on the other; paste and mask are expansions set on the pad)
0201 [mm] "SMD, 2-Leads, Height 0.33mm"
  rect 0.46x0.42 smd mask+0.025: 1(-0.33,0) 2(0.33,0)
  body extent -0.31,-0.16 0.31,0.16, height 0.33
0402#1 [mm] "0402 from SM-752 data"
  rect 0.8x0.6 smd: 1(-0.6,0) 2(0.6,0)
  silkscreen extent -1.22,-0.52 1.22,0.52, body extent -0.55,-0.3 0.55,0.3, height 0.6
0402#2 [mm] "Chip Capacitor, Body 1.0x0.5mm, IPC High Density"
  rect 0.6x0.5 smd: 1(-0.5,0) 2(0.5,0)
  body extent -0.55,-0.3 0.55,0.3, height 1.3
0603 [mm] "0603 from SM-752 data"
  rect 1x0.95 smd: 1(-0.8,0) 2(0.8,0)
  silkscreen extent -1.52,-0.69 1.52,0.69, body extent -0.87,-0.47 0.87,0.47, height 1
0805 [mm] "0805 from SM-752 data"
  rect 1.3x1.5 smd: 1(-0.85,0) 2(0.85,0)
  silkscreen extent -1.72,-0.97 1.72,0.97, body extent -1.1,-0.72 1.1,0.72, height 1.45
0805_HV [mil] "0805 with 30mil clearance between pads"
  rect 50x63 smd: 1(-40,0) 2(40,0)
  silkscreen extent -74,-40 74,40, body extent -43,-29 43,29, height 57
AssemblyNote [mil] "Assembly Note"
C603 [mil]
  rect 30x40 smd mask+2: 1(-35,0) 2(35,0)
C0805 [mm] "Chip Capacitor, Body 2.0x1.3mm, IPC High Density"
  rect 1.1x1.4 smd: 1(-0.75,0) 2(0.75,0)
  body extent -1.1,-0.72 1.1,0.73, height 1.4
CAPSMT_62_E55 [mm] "5 x 5.2mm:  Chemi-Con E55"
  rect 3x1.6 smd: 1(-2.2,0) 2(2.2,0)
  silkscreen extent -2.75,-2.75 2.75,2.75, body extent -2.75,-2.75 2.75,2.75, height 5.5
CONN_5103308-1 [mm] "TE Connectivity (AMP) Rev E datasheet"
  rect 1.65x1.65 hole 1.016 mask+0: 1(-5.08,-1.27)
  round 1.65 hole 1.016 mask+0: 2(-5.08,1.27) 3(-2.54,-1.27) 4(-2.54,1.27) 5(0,-1.27) 6(0,1.27) 7(2.54,-1.27) 8(2.54,1.27) 9(5.08,-1.27) 10(5.08,1.27)
  silkscreen extent -10.16,-5.72 10.16,4.57, body extent -10.16,-4.57 10.16,4.57, height 9.87
CONN_PEC05DAAN [mm] "SULLINS"
  rect 1.65x1.65 hole 1.016 mask+0: 1(-5.08,-1.27)
  round 1.65 hole 1.016 mask+0: 2(-5.08,1.27) 3(-2.54,-1.27) 4(-2.54,1.27) 5(0,-1.27) 6(0,1.27) 7(2.54,-1.27) 8(2.54,1.27) 9(5.08,-1.27) 10(5.08,1.27)
  silkscreen extent -6.35,-3.68 6.35,2.54, body extent -6.35,-2.54 6.35,2.54, height 8.38
CONN_USB-MINI-B-1734035-2 [mm] "Tyco Connectivity recommended land pattern"
  rect 0.5x2.3 smd: 1(-1.6,2.6) 2(-0.8,2.6) 3(0,2.6) 4(0.8,2.6) 5(1.6,2.6)
  rect 2x2.5 smd: 6(4.45,2.5) 7(4.45,-3) 8(-4.45,-3) 9(-4.45,2.5)
  round 0.9 hole 0.9 unplated: 10(2.2,0) 11(-2.2,0)
  silkscreen extent -5,-5 4.9,5.28, body extent -4.95,-5.9 4.95,3.3, height 4.1
DRB0008A [mm] "SON, 8-Leads, Body 3x3mm, Pitch 0.65mm, Thermal Pad 1.75x1.5mm, TI Recommended"
  rrect33% 0.6x0.3 smd: 1(-1.4,0.975) 2(-1.4,0.325) 3(-1.4,-0.325) 4(-1.4,-0.975) 5(1.4,-0.975) 6(1.4,-0.325) 7(1.4,0.325) 8(1.4,0.975)
  rrect7% 1.5x1.75 smd paste-0.75: 9(0,0)
  Top Layer region: -0.465,-1.5 -0.465,-0.875 -0.75,-0.875 -0.75,0.875 -0.465,0.875 -0.465,1.5 -0.185,1.5 -0.185,0.875 0.185,0.875 0.185,1.5 0.465,1.5 0.465,0.875 0.75,0.875 0.75,-0.875 0.465,-0.875 0.465,-1.5 0.185,-1.5 0.185,-0.875 -0.185,-0.875 -0.185,-1.5
  silkscreen extent -2.29,-1.73 1.73,1.73, body extent -1.58,-1.57 1.58,1.58, height 1.01
DRY0006A [mm] "PSON, 6-Leads, Body 1x1.45mm, Pitch 0.5mm, TI Recommended"
  rect 0.35x0.2 smd: 1(-0.275,0.5)
  rect 0.3x0.2 smd: 2(-0.3,0) 3(-0.3,-0.5) 4(0.3,-0.5) 5(0.3,0) 6(0.3,0.5)
  silkscreen extent -1.14,-0.85 0.2,0.85, body extent -0.53,-0.75 0.53,0.75, height 0.61
EMERSON_142-0771-821 [mil] "Recommended land pattern dr-142-0771-821.pdf dated 11-3-04"
  rect 28.5x75 smd: 1(0,75)
  round 60 hole 45.3 mask+2: 2(-56.5,43.5) 3(-56.5,-43.5) 4(56.5,-43.5) 5(56.5,43.5)
  Top Layer region: 24.25,-105.47 160,-105.47 160,112.53 24.25,112.53
  Top Layer region: -24.25,112.53 -160,112.53 -160,-105.47 -24.25,-105.47
  body extent -125,-67 125,488, height 131
FCC_disclaimer_stacked [mil]
Fiducial10-30 [mm]
  round 1 smd mask+1: 1(0,0)
  Top Layer keep-out circle w1.678: c0,0 r0.75
Keystone_1212-ST [mm] "Disconnect Terminal, 5.08mm, 2x1, TH"
  round 1.85 hole 1.32: 1(-2.54,0) 2(2.54,0)
  silkscreen extent -3.75,-1.5 3.75,1.5, body extent -3.64,-1.51 3.56,1.55, height 9.43
Keystone_1902C [mil] "Hex Standoff, 4-40 threaded, nylon"
  round 1 on Mech4: 0(0,0)
  body extent -145,-126 146,126, height 501
LED_SML-LX0603GW [mm] "LUMEX OPTO"
  rect 0.8x0.8 smd: 1(-0.75,0) 2(0.75,0)
  silkscreen extent 1.4,-0.4 1.8,0.4, body extent -0.8,-0.4 0.8,0.4, height 0.6
"NY PMS 440 0025 PH" [mm] "4-40 nylon screw and mounting hole"
  round 8 hole 3.2 unplated: 1(0,0)
  body extent -3.3,-3.3 3.3,3.3, height 2.69
Pb-Free_Overlay_Small [mil]
  silkscreen extent -46,-46 46,46
PN0080A_N [mm] "QFP, 80-Leads, Body 12x12mm, Pitch 0.5mm, IPC Medium Density"
  oval 1.45x0.3 smd: 1(-6.725,4.75) 2(-6.725,4.25) 3(-6.725,3.75) 4(-6.725,3.25) 5(-6.725,2.75) 6(-6.725,2.25) 7(-6.725,1.75) 8(-6.725,1.25) 9(-6.725,0.75) 10(-6.725,0.25) 11(-6.725,-0.25) 12(-6.725,-0.75) 13(-6.725,-1.25) 14(-6.725,-1.75) 15(-6.725,-2.25) 16(-6.725,-2.75) 17(-6.725,-3.25) 18(-6.725,-3.75) 19(-6.725,-4.25) 20(-6.725,-4.75) 41(6.725,-4.75) 42(6.725,-4.25) 43(6.725,-3.75) 44(6.725,-3.25) 45(6.725,-2.75) 46(6.725,-2.25) 47(6.725,-1.75) 48(6.725,-1.25) 49(6.725,-0.75) 50(6.725,-0.25) 51(6.725,0.25) 52(6.725,0.75) 53(6.725,1.25) 54(6.725,1.75) 55(6.725,2.25) 56(6.725,2.75) 57(6.725,3.25) 58(6.725,3.75) 59(6.725,4.25) 60(6.725,4.75)
  oval 0.3x1.45 smd: 21(-4.75,-6.725) 22(-4.25,-6.725) 23(-3.75,-6.725) 24(-3.25,-6.725) 25(-2.75,-6.725) 26(-2.25,-6.725) 27(-1.75,-6.725) 28(-1.25,-6.725) 29(-0.75,-6.725) 30(-0.25,-6.725) 31(0.25,-6.725) 32(0.75,-6.725) 33(1.25,-6.725) 34(1.75,-6.725) 35(2.25,-6.725) 36(2.75,-6.725) 37(3.25,-6.725) 38(3.75,-6.725) 39(4.25,-6.725) 40(4.75,-6.725) 61(4.75,6.725) 62(4.25,6.725) 63(3.75,6.725) 64(3.25,6.725) 65(2.75,6.725) 66(2.25,6.725) 67(1.75,6.725) 68(1.25,6.725) 69(0.75,6.725) 70(0.25,6.725) 71(-0.25,6.725) 72(-0.75,6.725) 73(-1.25,6.725) 74(-1.75,6.725) 75(-2.25,6.725) 76(-2.75,6.725) 77(-3.25,6.725) 78(-3.75,6.725) 79(-4.25,6.725) 80(-4.75,6.725)
  silkscreen extent -6.85,-5.6 5.6,5.6, body extent -7,-7 7,7, height 1.56
R603 [mil]
  rect 30x40 smd mask+1.97: 1(-35,0) 2(35,0)
  silkscreen extent -65,-35 65,35
RTV0032E-MFG [mm]
  rect 0.85x0.28 smd mask+0.038: 1(-2.475,1.75) 2(-2.475,1.25) 3(-2.475,0.75) 4(-2.475,0.25) 5(-2.475,-0.25) 6(-2.475,-0.75) 7(-2.475,-1.25) 8(-2.475,-1.75) 17(2.475,-1.75) 18(2.475,-1.25) 19(2.475,-0.75) 20(2.475,-0.25) 21(2.475,0.25) 22(2.475,0.75) 23(2.475,1.25) 24(2.475,1.75)
  rect 0.28x0.85 smd mask+0.038: 9(-1.75,-2.475) 10(-1.25,-2.475) 11(-0.75,-2.475) 12(-0.25,-2.475) 13(0.25,-2.475) 14(0.75,-2.475) 15(1.25,-2.475) 16(1.75,-2.475) 25(1.75,2.475) 26(1.25,2.475) 27(0.75,2.475) 28(0.25,2.475) 29(-0.25,2.475) 30(-0.75,2.475) 31(-1.25,2.475) 32(-1.75,2.475)
  rect 3.45x3.45 smd paste-1000 mask+0.038: 33(0,0)
  silkscreen extent -3.33,-2.8 2.8,2.8, body extent -2.55,-2.55 2.55,2.55
SAMTEC_BNC7T-J-P-GN-ST-EM1D [mm] "Connector, Edge Mount, SMD"
  rect 1.5x1.8 smd: 1(0,-2.2)
  rect 1.35x6.8 smd: 2(-4.82,-3.4) 3(4.82,-3.4)
  rect 1.5x6.8 smd far side: 4(-4.25,-3.4) 5(4.25,-3.4)
  silkscreen extent -8.01,-7.25 8.01,-0.3, body extent -7.98,-6.34 7.98,19.14, height 8.62
SMB [mil] "Molded Diode, 2-Leads, Body 5.4x3.6mm, IPC Medium Density, based on OnSemi component dimensions"
  rect 85x107.99 smd: 1(-87.01,0) 2(87.01,0)
  silkscreen extent -155,-82 125,82, body extent -106,-71 106,71, height 91
SNT-100-BK-G [mil] "Samtec STEP model"
  round 1 on Mech3: 0(0,0)
  body extent -100,-50 100,50, height 344
SOT-23 [mm] "SOT23, 3-Leads, Body 2.9x1.3mm, Pitch 0.95mm, Lead Span 2.5mm, IPC Medium Density"
  rrect50% 1x0.6 smd: 1(-1.2,0.95) 2(-1.2,-0.95) 3(1.2,0)
  silkscreen extent -1.63,-1.5 0.7,1.5, body extent -1.16,-1.45 1.21,1.45, height 1
TE_5-146254-3 [mm] "TE 100mil, 3x2"
  rrect50% 1.65x1.65 hole 1.016: 1(-2.54,-1.27)
  round 1.65 hole 1.016: 2(-2.54,1.27) 3(0,-1.27) 4(0,1.27) 5(2.54,-1.27) 6(2.54,1.27)
  silkscreen extent -3.61,-3.68 3.61,2.44, body extent -3.61,-2.44 3.61,2.44, height 8.14
TE_5-146278-2 [mm] "TE CONNECTIVITY"
  rect 1.65x1.65 hole 1: 1(-1.27,0)
  round 1.65 hole 1: 2(1.27,0)
  silkscreen extent -2.54,-2.41 2.54,1.27, body extent -2.41,-1.17 2.41,1.17, height 8.13
TE_5-146278-3 [mm] "TE CONNECTIVITY"
  rect 1.65x1.65 hole 1: 1(-2.54,0)
  round 1.65 hole 1: 2(0,0) 3(2.54,0)
  silkscreen extent -3.81,-2.41 3.81,1.27, body extent -3.68,-1.17 3.68,1.17, height 8.13
TI_Stacked_Overlay_Small [mil]
  silkscreen extent -418,-98 418,98
TL3901AGQF180 [mm]
  rect 1.4x1.5 smd mask+0.038: 1(-1.7,-2.9) 2(1.7,-2.9) 3(-1.7,2.9) 4(1.7,2.9)
  round 0.9 hole 0.9 unplated mask+0.038: ""(-1.5,0) ""(1.5,0)
  silkscreen extent -2.95,-4.6 4.8,3.25, body extent -2.7,-3 4.55,3, height 1.9
TSW-102-07-G-D [mm] "Samtec 100mil, 2x2, 230 mil above insulator"
  rrect6% 1.65x1.65 hole 1.016: 1(-1.27,-1.27)
  round 1.65 hole 1.016: 2(-1.27,1.27) 3(1.27,-1.27) 4(1.27,1.27)
  silkscreen extent -2.54,-3.68 2.54,2.54, body extent -2.54,-2.54 2.54,2.54, height 8.38
XTAL_CSM-7X [mm] "ECS"
  rect 5.5x2 smd: 1(-4.75,0) 2(4.75,0)
  silkscreen extent -6.2,-2.5 6.2,2.5, body extent -5.95,-2.4 5.95,2.4, height 4.3

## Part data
C1: "CAP, CERM, 10uF, 16V, +/-20%, X5R, 0805", Cap_Case=0805, Manufacturer=AVX, Supplier Part Number 1=1582704, TempCo=X5R, Tolerance_%=20, Value1=Unknown, Value2=16V, ValueDisplayed=10µF
C2: "CAP, CERM, 1uF, 16V, +/-10%, X5R, 0805", Cap_Case=0805, Manufacturer=AVX, Supplier Part Number 1=478-1411-1-ND, TempCo=X5R, Tolerance_%=10, Value1="0.012 ohm", Value2=16V, ValueDisplayed=1µF
C3 C9 C10 C11 C13 C13_1 C14 C15 C16 C17 C18: "CAP, CERM, 4.7 µF, 10 V, +/- 10%, X5R, 0402", Cap_Case=0402, Manufacturer=TDK, Supplier Part Number 1=445-13820-1-ND, TempCo=X5R, Tolerance_%=10, Value1=Unknown, Value2=10V, ValueDisplayed=4.7µF
C4 C5 C7: library part CMP-0006255-1, "CAP, CERM, 0.1 uF, 6.3 V, +/- 10%, X5R, 0402", Cap_Case=0402, Manufacturer=TDK, Supplier Part Number 1=445-1266-1-ND, TempCo=X5R, Tolerance_%=10%, Value1="0.0186 ohm", Value2=6.3V, ValueDisplayed=0.1uF
C6: "CAP, CERM, 1 µF, 6.3 V, +/- 20%, X5R, 0402", Cap_Case=0402, Manufacturer=TDK, Supplier Part Number 1=445-1415-1-ND, TempCo=X5R, Tolerance_%=20, Value1="0.0079 ohm", Value2=6.3V, ValueDisplayed=1µF
C8: library part CMP-0008868-2, "CAP CER 0.47UF 16V X5R 0201", Cap_Case=0201, Manufacturer="Taiyo Yuden", TempCo=X7R, Tolerance_%=10%, Value1=Unknown, Value2=16V, ValueDisplayed=0.47uF
C21: "CAP, CERM, 2.2uF, 16V, +/-10%, X5R, 0805", Alternate Manufacturer=-, Cap_Case=0805, Manufacturer=AVX, Supplier Part Number 1=478-2580-1-ND, TempCo=X5R, Tolerance_%=10, Value1="0.009 ohm", Value2=16V, ValueDisplayed=2.2µF
C22: "CAP, AL, 22 µF, 10 V, +/- 20%,  ohm, SMD", Cap_Case=E55, Manufacturer=Chemi-Con, Supplier Part Number 1=565-2185-1-ND, Tolerance_%=20, Value1=Unknown, Value2=10V, ValueDisplayed=22µF
C23: "CAP, CERM, 1 µF, 16 V, +/- 10%, X5R, 0805", Cap_Case=0805, Manufacturer=AVX, Supplier Part Number 1=478-1411-1-ND, TempCo=X5R, Tolerance_%=10, Value1="0.012 ohm", Value2=16V, ValueDisplayed=1µF
C24: "CAP, CERM, 0.01 µF, 50 V, +/- 10%, X7R, 0603", Cap_Case=0603, Manufacturer=TDK, Supplier Part Number 1=445-1311-1-ND, TempCo=X7R, Tolerance_%=10, Value1="0.0539 ohm", Value2=50V, ValueDisplayed=0.01µF
C25 C31 C32 C34: "CAP, CERM, 0.1uF, 16V, +/-5%, X7R, 0603", Alternate Manufacturer=-, Cap_Case=0603, Manufacturer=AVX, Supplier Part Number 1=478-3726-1-ND, TempCo=X7R, Tolerance_%=5, Value1="0.039 ohm", Value2=16V, ValueDisplayed=0.1µF
C26 C27: "CAP, CERM, 220pF, 50V, +/-1%, C0G/NP0, 0603", Alternate Manufacturer=-, Cap_Case=0603, Manufacturer=AVX, Supplier Part Number 1=478-3719-1-ND, TempCo=C0G/NP0, Tolerance_%=1, Value1="0.083 ohm", Value2=50V, ValueDisplayed=220pF
C28 C29: "CAP, CERM, 30pF, 100V, +/-5%, C0G/NP0, 0603", Alternate Manufacturer=-, Cap_Case=0603, Manufacturer=MuRata, Supplier Part Number 1=490-1338-1-ND, TempCo=C0G/NP0, Tolerance_%=5, Value1=?, Value2=100V, ValueDisplayed=30pF
C30: "CAP, CERM, 2200pF, 50V, +/-10%, X7R, 0603", Alternate Manufacturer=-, Cap_Case=0603, Manufacturer=Kemet, Supplier Part Number 1=399-5341-1-ND, TempCo=X7R, Tolerance_%=10, Value1=?, Value2=50V, ValueDisplayed=2200pF
C33: "CAP, CERM, 0.47uF, 10V, +/-10%, X7R, 0603", Alternate Manufacturer=-, Cap_Case=0603, Manufacturer=MuRata, Supplier Part Number 1=GRM188R71A474KA61D-ND, TempCo=X7R, Tolerance_%=10, Value1=?, Value2=10V, ValueDisplayed=0.47µF
D1 D3: "LED, Green, SMD", Color=green, Manufacturer=Lumex, Supplier Part Number 1=67-1549-1-ND, Value1=W, Value2=2.2V
D2: "Diode, Zener, 7.5 V, 550 mW, SMB", Manufacturer="ON Semiconductor", Power_W=0.55, Supplier Part Number 1=863-1SMB5922BT3G, Value1=0.55W
FB1: library part BK1608HS600-T, "FERRITE BEAD 60 OHM 0603 1LN", Manufacturer="Laird-Signal Integrity Products", Value1="0.1 ohm", Value2=0.8A
FID1 FID2 FID3 FID4 FID5 FID6: "Fiducial mark.  There is nothing to buy or mount.", Manufacturer=N/A
H1 H2 H3 H4: "Machine Screw, Round, #4-40 x 1/4, Nylon, Philips panhead", DigiKeyPartNumber=H542-ND, Manufacturer="B&F Fastener Supply"
H5 H6 H7 H8: "Standoff, Hex, 0.5\"L #4-40 Nylon", Manufacturer=Keystone, Supplier Part Number 1=1902CK-ND
J1 J2: "Disconnect Terminal, 5.08mm, 2x1, Tin, TH", Manufacturer=Keystone, Supplier Part Number 1=36-1212-ST-ND
J3 J4: "Connector, BNC Edge Mount, SMD", Manufacturer=Samtec
J5: "Header, 100mil, 3x1, Tin, TH", Manufacturer="TE Connectivity", Supplier Part Number 1=5-146278-3-ND
J6 J7: "Header, 100mil, 2x1, Tin, TH", Manufacturer="TE Connectivity", Supplier Part Number 1=5-146278-2-ND
J8: "Header (shrouded), 100mil, 5x2, Gold, TH", Manufacturer="TE Connectivity", Supplier Part Number 1=A33159-ND
J9: "Header, 100mil, 5x2, Tin, TH", Manufacturer="Sullins Connector Solutions", Supplier Part Number 1=S2012E-05-ND
J10 J11 J12 J13 J14 J15 J16 J17 J18 J19: "Header, 100mil, 3x2, Tin, TH", Manufacturer="TE Connectivity"
J20 J21 J23 J25: library part CMP-0055824-1, "Connector, End launch SMA 50 ohm, TH", Manufacturer="Cinch Connectivity", Supplier Part Number 1=J807-ND
J22 J32: library part BNC7T-J-P-GN-ST-EM1D, "Connector, BNC Edge Mount, SMD", Manufacturer=Samtec
J31: library part 1734035-2, "Connector, Receptacle, Mini-USB Type B, R/A, Top Mount SMT", Manufacturer="TE Connectivity", Supplier Part Number 1=A31727CT-ND
J33: "Header, 100mil, 2x2, Gold, TH", Manufacturer=Samtec, Supplier Part Number 1=SAM1028-02-ND
Logo1: library part TI_Logo, "Texas Instrument Corporate Signature"
Logo2: library part Pb-Free
Logo3: library part FCC_disclaimer, "FCC_disclaimer"
Q1: "MOSFET, N-CH, 50 V, 0.22 A, SOT-23", Alternate Manufacturer=None, Manufacturer="Fairchild Semiconductor", Supplier Part Number 1=BSS138CT-ND, Value1="6 ohm", Value2="1.7 nC"
R1 R2: "RES, 2.00k ohm, 1%, 0.063W, 0402", Manufacturer=Vishay-Dale, Power_W=0.063, Supplier Part Number 1=541-2.00KLCT-ND, TempCo="100 ppm/C", Tolerance_%=1, Value1=1%, Value2=0.063W, Value_Code=2k00
R3 R4 R5 R6 R7 R8 R9 R10 R11 R12 R13 R14 R15 R16 R17 R18 R19 R20 R41 R42: "RES, 1.00k ohm, 1%, 0.063W, 0402", Manufacturer=Vishay-Dale, Power_W=0.063, Supplier Part Number 1=541-1.00KLCT-ND, TempCo="100 ppm/C", Tolerance_%=1, Value1=1%, Value2=0.063W, Value_Code=1k00
R21: "RES, 220 ohm, 5%, 0.063W, 0402", Manufacturer=Vishay-Dale, Power_W=0.063, Supplier Part Number 1=541-220JCT-ND, TempCo="200 ppm/C", Tolerance_%=5, Value1=5%, Value2=0.063W, Value_Code=220R
R22 R23 R24: "RES, 3.16k ohm, 1%, 0.063W, 0402", Manufacturer=Vishay-Dale, Power_W=0.063, Supplier Part Number 1=541-3.16KLCT-ND, TempCo="100 ppm/C", Tolerance_%=1, Value1=1%, Value2=0.063W, Value_Code=3k16
R25 R26 R27: "RES, 9.76k ohm, 1%, 0.063W, 0402", Manufacturer=Vishay-Dale, Power_W=0.063, Supplier Part Number 1=541-9.76KLCT-ND, TempCo="100 ppm/C", Tolerance_%=1, Value1=1%, Value2=0.063W, Value_Code=9k76
R28 R29 R30 R40: library part CRCW04023K16FKED, "RES SMD 75 OHM 1% 1/5W 0402", Manufacturer="Panasonic Electronic Components", Power_W=0.063, TempCo="100 ppm/C", Tolerance_%=1, Value1=1%, Value2=0.2W, Value_Code=75
R31 R32: "RES, 33 ohm, 5%, 0.063W, 0402", Alternate Manufacturer=-, Manufacturer=Vishay-Dale, Power_W=0.063, Supplier Part Number 1=541-33JCT-ND, TempCo="200 ppm/C", Tolerance_%=5, Value1=5%, Value2=0.063W, Value_Code=33R0
R33: "RES, 1.5 k, 5%, 0.063 W, 0402", Manufacturer=Vishay-Dale, Power_W=0.063, Supplier Part Number 1=541-1.5KJCT-ND, TempCo="200 ppm/C", Tolerance_%=5, Value1=5%, Value2=0.063W, Value_Code=1k50, ValueDisplayed=1.5k
R34 R36: "RES, 33k ohm, 5%, 0.063W, 0402", Alternate Manufacturer=-, Manufacturer=Vishay-Dale, Power_W=0.063, Supplier Part Number 1=541-33KJCT-ND, TempCo="200 ppm/C", Tolerance_%=5, Value1=5%, Value2=0.063W, Value_Code=33k0
R35: "RES, 1.2Meg ohm, 5%, 0.1W, 0603", Alternate Manufacturer=-, Manufacturer=Vishay-Dale, Power_W=0.1, Supplier Part Number 1=541-1.2MGCT-ND, TempCo="200 ppm/C", Tolerance_%=5, Value1=5%, Value2=0.1W, Value_Code=1M20
R37: "RES, 200 ohm, 1%, 0.1W, 0603", Alternate Manufacturer=-, Manufacturer=Vishay-Dale, Power_W=0.1, Supplier Part Number 1=541-200HCT-ND, TempCo="100 ppm/C", Tolerance_%=1, Value1=1%, Value2=0.1W, Value_Code=200R
R43 R44 R45 R46 R47 R48 R49 R50 R51 R52: "RES, 20.0k ohm, 1%, 0.063W, 0402", Manufacturer=Vishay-Dale, Power_W=0.063, Supplier Part Number 1=541-20.0KLCT-ND, TempCo="100 ppm/C", Tolerance_%=1, Value1=1%, Value2=0.063W, Value_Code=20k0
S1: library part EVQ-PSD02K, "Switch, Tactile, SPST-NO, SMT", CurrentRating_mA=50, Manufacturer=E-Switch
SH-J2 SH-J3 SH-J4 SH-J5 SH-J6 SH-J7 SH-J8 SH-J9 SH-J10 SH-J11 SH-J12 SH-J13: "Shunt, 100mil, Gold plated, Black", Alternate Manufacturer=Samtec, Alternate PartNumber=SNT-100-BK-G, Manufacturer=3M, Supplier Part Number 1=3M9580-ND
U1: library part CMP-0094574-1, "12G UHD-SDI Long Reach Adaptive Cable Equalizer with Integrated Reclocker Product Requirement Specifications (PRS), WQFN32", Manufacturer="Texas Instruments", Max Supply Voltage=2.625V, Min Supply Voltage=2.375V, Operating Temperature Range=to
U2: "500mA, Low Quiescent Current, Ultra-Low Noise, High PSRR Low-Dropout Linear Regulator, DRB0008A", Alternate Manufacturer="Texas Instruments", Alternate PartNumber=TPS73533DRBT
